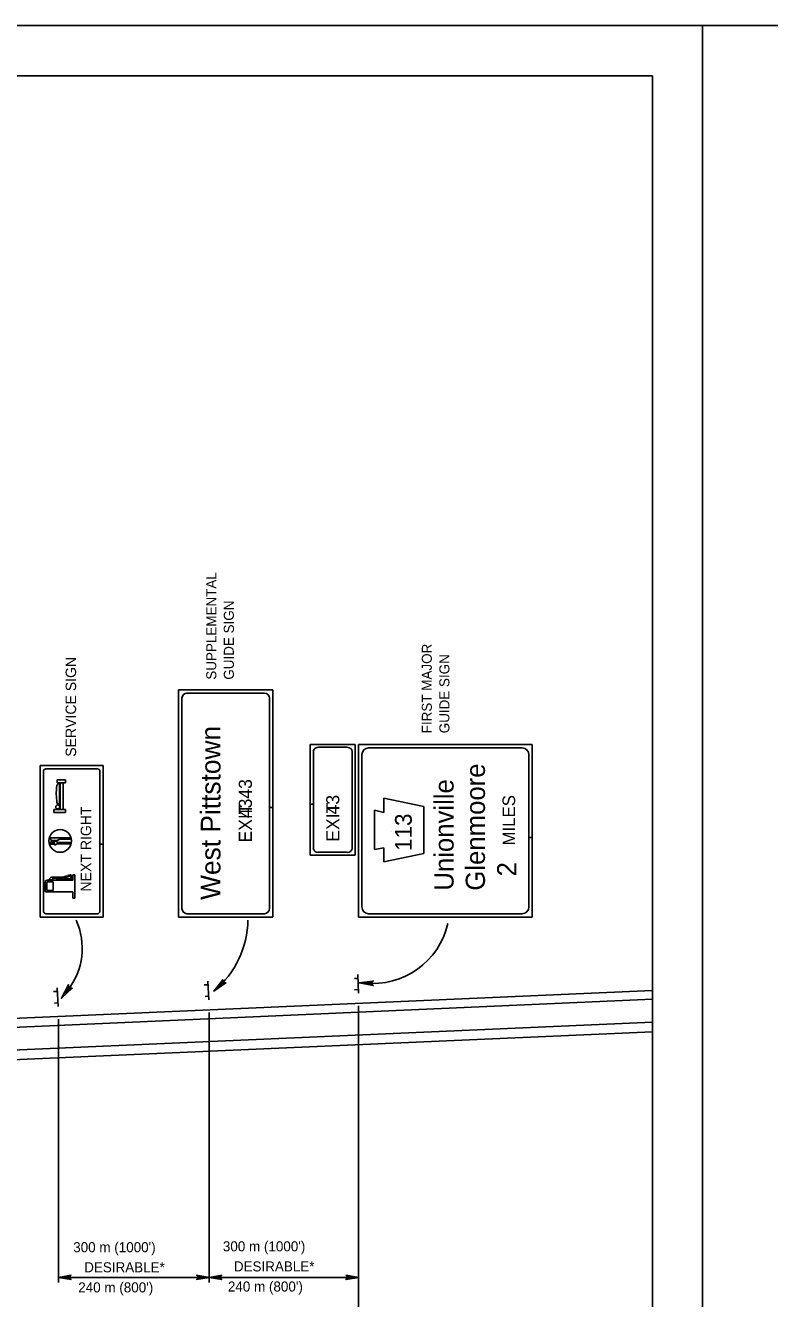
# Model space of a CAD drawing. Extents: x 640994 to 644422, y 298458 to 299646.
# Drawn here: x 642474.1 to 642696.3, y 299265.4 to 299645.6 of the extents above; entities that cross this region are included whole.
import ezdxf

# ---------------------------------------------------------------- set-up
doc = ezdxf.new("R2010")
doc.units = 0
for name, color, linetype in [('1', 7, 'Continuous'), ('2', 7, 'Continuous'), ('XCS-GRID-MIN', 7, 'Continuous')]:
    doc.layers.add(name, color=color, linetype=linetype)

msp = doc.modelspace()

# ---------------------------------------------------------------- linework, layer by layer
at = {"layer": '1'}
for p in [(641875.31, 299630.63), (642661.31, 299066.63)]:
    msp.add_line(p, (642661.31, 299630.63), dxfattribs=at)
at = {"layer": '2'}
for p, q in [((642547.94, 299447.25), (642519.81, 299447.25)), ((642519.81, 299447.25), (642519.81, 299379.38)), ((642522.31, 299446.25), (642522.31, 299446.25)), ((642522.31, 299446.25), (642545.44, 299446.25)), ((642545.44, 299446.25), (642545.44, 299446.25)), ((642547.94, 299412.11), (642547.94, 299447.25)), ((642520.81, 299381.88), (642520.81, 299444.75)), ((642546.94, 299444.75), (642546.94, 299412.11)), ((642559.06, 299413.05), (642559.06, 299430.88)), ((642559.06, 299430.88), (642572.56, 299430.88)), ((642572.56, 299430.88), (642572.56, 299397.88)), ((642625.44, 299430.88), (642573.56, 299430.88)), ((642573.56, 299430.88), (642573.56, 299379.38)), ((642625.44, 299403.13), (642625.44, 299430.88)), ((642560.06, 299428.75), (642560.06, 299413.05)), ((642570.19, 299430.13), (642561.44, 299430.13)), ((642571.69, 299399.88), (642571.69, 299428.75)), ((642574.56, 299382.38), (642574.56, 299427.88)), ((642576.56, 299429.88), (642622.44, 299429.88)), ((642624.44, 299427.88), (642624.44, 299403.13)), ((642478.44, 299379.38), (642478.44, 299424.63)), ((642478.44, 299424.63), (642497.31, 299424.63)), ((642495.56, 299423.63), (642480.19, 299423.63)), ((642497.31, 299424.63), (642497.31, 299401.1)), ((642479.44, 299422.88), (642479.44, 299381.13)), ((642483.56, 299419.5), (642483.56, 299420.38)), ((642483.56, 299420.38), (642486.06, 299420.38)), ((642483.56, 299419.5), (642486.06, 299419.5)), ((642484.44, 299411.5), (642484.44, 299419.5)), ((642485.31, 299411.5), (642485.31, 299419.5)), ((642486.06, 299419.5), (642486.06, 299420.38)), ((642496.31, 299401.1), (642496.31, 299422.88)), ((642484.19, 299413), (642484.19, 299419.25)), ((642484.44, 299415.5), (642484.44, 299415.5)), ((642546.94, 299412.11), (642547.94, 299412.11)), ((642547.94, 299412.11), (642546.94, 299412.11)), ((642546.94, 299412.11), (642546.94, 299381.88)), ((642547.94, 299379.38), (642547.94, 299412.11)), ((642559.06, 299413.05), (642560.06, 299413.05)), ((642560.06, 299413.05), (642559.06, 299413.05)), ((642559.06, 299397.88), (642559.06, 299413.05)), ((642560.06, 299413.05), (642560.06, 299399.88)), ((642565.81, 299414.38), (642565.81, 299414.38)), ((642581.06, 299410.63), (642581.06, 299414.88)), ((642581.06, 299414.88), (642593.06, 299412.38)), ((642593.06, 299412.38), (642593.06, 299405.25)), ((642615.31, 299411.75), (642615.31, 299411.75)), ((642486.06, 299411.5), (642482.56, 299411.5)), ((642482.56, 299410.63), (642482.56, 299411.5)), ((642486.06, 299410.63), (642482.56, 299410.63)), ((642486.06, 299410.63), (642486.06, 299411.5)), ((642578.31, 299405.38), (642578.31, 299411.25)), ((642578.31, 299411.25), (642581.06, 299410.63)), ((642578.31, 299399.5), (642578.31, 299405.38)), ((642583.44, 299404.88), (642583.44, 299404.88)), ((642583.44, 299404.88), (642583.44, 299404.88)), ((642583.44, 299404.88), (642583.44, 299404.88)), ((642583.44, 299404.88), (642583.44, 299404.88)), ((642593.06, 299405.5), (642593.06, 299398.38)), ((642481.44, 299401.75), (642482.56, 299402)), ((642482.81, 299401.63), (642481.44, 299401.75)), ((642482.81, 299401.5), (642481.44, 299401.63)), ((642481.44, 299401.63), (642482.81, 299401.63)), ((642481.44, 299401.38), (642482.44, 299401.5)), ((642482.94, 299401.25), (642481.44, 299401.38)), ((642481.44, 299401.13), (642482.94, 299401.25)), ((642482.81, 299401), (642481.44, 299401.13)), ((642487.31, 299403), (642481.56, 299403)), ((642481.56, 299403), (642481.56, 299402.75)), ((642483.56, 299402.25), (642481.94, 299402.25)), ((642482.44, 299401.5), (642482.81, 299401.5)), ((642487.31, 299401.63), (642483.69, 299401.63)), ((642487.31, 299401.25), (642483.69, 299401.25)), ((642487.31, 299402.63), (642484.19, 299402.63)), ((642496.31, 299401.1), (642497.31, 299401.1)), ((642497.31, 299401.1), (642496.31, 299401.1)), ((642496.31, 299381.13), (642496.31, 299401.1)), ((642497.31, 299401.1), (642497.31, 299379.38)), ((642624.44, 299403.13), (642625.44, 299403.13)), ((642625.44, 299403.13), (642624.44, 299403.13)), ((642624.44, 299403.13), (642624.44, 299382.38)), ((642625.44, 299379.38), (642625.44, 299403.13)), ((642572.56, 299397.88), (642559.06, 299397.88)), ((642561.44, 299398.75), (642570.19, 299398.75)), ((642581.06, 299400), (642578.31, 299399.5)), ((642581.06, 299395.88), (642581.06, 299400)), ((642593.06, 299398.38), (642581.06, 299395.88)), ((642479.94, 299387.25), (642479.94, 299389.88)), ((642488.19, 299390.38), (642480.31, 299390.38)), ((642482.19, 299389.88), (642480.44, 299389.88)), ((642480.44, 299387.5), (642480.44, 299389.75)), ((642480.81, 299390.38), (642481.44, 299391)), ((642481.44, 299390.5), (642481.31, 299390.38)), ((642482.19, 299390.5), (642481.44, 299390.5)), ((642481.94, 299391.25), (642485.19, 299391.25)), ((642482.19, 299391), (642485.19, 299391)), ((642482.19, 299391), (642482.19, 299390.5)), ((642482.31, 299387.5), (642482.31, 299389.63)), ((642483.31, 299390.38), (642483.31, 299390.5)), ((642483.56, 299390.75), (642486.81, 299390.75)), ((642483.56, 299390.38), (642483.56, 299390.38)), ((642483.69, 299390.5), (642487.31, 299390.5)), ((642485.81, 299391.5), (642486.56, 299391.63)), ((642485.94, 299391.13), (642486.69, 299391.38)), ((642488.19, 299390.38), (642488.19, 299392)), ((642488.81, 299392), (642488.19, 299392)), ((642488.81, 299385), (642488.81, 299392)), ((642488.19, 299386.88), (642480.31, 299386.88)), ((642482.19, 299387.25), (642480.44, 299387.25)), ((642488.19, 299385), (642488.19, 299386.88)), ((642488.81, 299385), (642488.19, 299385)), ((642497.31, 299379.38), (642478.44, 299379.38)), ((642480.19, 299380.38), (642495.56, 299380.38)), ((642519.81, 299379.38), (642547.94, 299379.38)), ((642522.31, 299380.38), (642522.31, 299380.38)), ((642545.44, 299380.38), (642522.31, 299380.38)), ((642545.44, 299380.38), (642545.44, 299380.38)), ((642573.56, 299379.38), (642625.44, 299379.38)), ((642622.44, 299380.38), (642576.56, 299380.38)), ((642573.31, 299362.25), (642573.56, 299356.63)), ((642528.56, 299359.13), (642527.44, 299359.13)), ((642528.56, 299360.25), (642528.81, 299354.63)), ((642573.44, 299361), (642572.31, 299361)), ((642170.44, 299333.13), (642661.31, 299354.84)), ((642300.56, 299341.63), (642661.31, 299357.46)), ((642483.56, 299357.13), (642482.44, 299357.13)), ((642483.56, 299358.25), (642483.81, 299352.63)), ((642528.69, 299355.75), (642527.69, 299355.63)), ((642573.56, 299357.75), (642572.31, 299357.63)), ((642483.81, 299353.75), (642482.69, 299353.63)), ((642528.94, 299352.38), (642528.94, 299352.38)), ((642528.94, 299350.88), (642528.94, 299270.25)), ((642573.56, 299354.38), (642573.56, 299354.38)), ((642573.56, 299352.88), (642573.56, 299234.75)), ((642171.94, 299326.5), (642661.31, 299347.96)), ((642483.94, 299348.88), (642483.94, 299270.25)), ((642297.31, 299329.13), (642661.31, 299345.09)), ((642528.94, 299271.75), (642483.94, 299271.75)), ((642573.56, 299271.75), (642528.94, 299271.75))]:
    msp.add_line(p, q, dxfattribs=at)
for points in [[(642487.78, 299358.09), (642487.52, 299358.19), (642484.82, 299355.14), (642487.78, 299358.09), (642488.03, 299358.11), (642484.82, 299355.14), (642487.1, 299358.52), (642486.95, 299358.76), (642484.82, 299355.14), (642486.92, 299359.13), (642486.95, 299358.76)], [(642533.69, 299359.7), (642533.31, 299359.8), (642530.36, 299357.21), (642533.69, 299359.7), (642533.94, 299359.72), (642530.36, 299357.21), (642533.03, 299360.16), (642533.01, 299360.4), (642530.36, 299357.21), (642533, 299360.65), (642533.01, 299360.4)], [(642577.56, 299359.25), (642577.56, 299359.5), (642573.69, 299359.75), (642577.56, 299359.25), (642577.94, 299358.88), (642573.69, 299359.75), (642577.56, 299359.88), (642577.69, 299360.25), (642573.69, 299359.75), (642577.94, 299360.25), (642577.69, 299360.25)], [(642487.44, 299271.25), (642487.31, 299271.5), (642483.94, 299271.75), (642487.44, 299271.25), (642487.69, 299271.13), (642483.94, 299271.75), (642487.31, 299271.88), (642487.44, 299272.13), (642483.94, 299271.75), (642487.69, 299272.38), (642487.44, 299272.13)], [(642525.44, 299272.25), (642525.56, 299272), (642528.94, 299271.75), (642525.44, 299272.25), (642525.19, 299272.38), (642528.94, 299271.75), (642525.56, 299271.63), (642525.44, 299271.38), (642528.94, 299271.75), (642525.19, 299271.13), (642525.44, 299271.38)], [(642532.44, 299271.25), (642532.31, 299271.5), (642528.94, 299271.75), (642532.44, 299271.25), (642532.69, 299271.13), (642528.94, 299271.75), (642532.31, 299271.88), (642532.44, 299272.13), (642528.94, 299271.75), (642532.69, 299272.38), (642532.44, 299272.13)], [(642570.06, 299272.25), (642570.19, 299272), (642573.56, 299271.75), (642570.06, 299272.25), (642569.81, 299272.38), (642573.56, 299271.75), (642570.19, 299271.63), (642570.06, 299271.38), (642573.56, 299271.75), (642569.81, 299271.13), (642570.06, 299271.38)]]:
    msp.add_lwpolyline(points, dxfattribs=at)
for centre, radius in [((642483.71, 299412.25), 0.598), ((642484.44, 299402.1), 3.38)]:
    msp.add_circle(centre, radius, dxfattribs=at)
for centre, radius, start, end in [((642522.31, 299444.75), 1.5, 90, 180), ((642545.44, 299444.75), 1.5, 0, 90), ((642576.56, 299427.88), 2, 90, 180), ((642622.44, 299427.88), 2, 0, 90), ((642480.19, 299422.88), 0.75, 90, 180), ((642495.56, 299422.88), 0.75, 0, 90), ((642484.19, 299418.52), 0.74, 84.1655, 172.9293), ((642498.81, 299416.24), 15.54, 171.2295, 181.1783), ((642502.02, 299416.2), 18.75, 180.8408, 188.1781), ((642484.26, 299413.87), 0.868, 202.8419, 269.9082), ((642481.93, 299402.7), 0.422, 180, 270), ((642482.81, 299401.21), 0.83, 44.7019, 103.537), ((642482.86, 299401.64), 0.724, 261.5401, 313.94), ((642483.74, 299400.8), 0.494, 95.8318, 139.6318), ((642483.69, 299402.09), 0.42, 224.9301, 269.654), ((642483.42, 299402.96), 0.696, 281.1263, 314.137), ((642484.17, 299402.21), 0.369, 83.1408, 137.1102), ((642487.26, 299402.79), 0.218, 261.5053, 98.4947), ((642487.26, 299401.48), 0.195, 258.6255, 101.3745), ((642480.33, 299389.94), 0.405, 97.9024, 178.9277), ((642480.6, 299389.69), 0.228, 107.0861, 183.3769), ((642482.02, 299390.47), 0.826, 95.5404, 137.2088), ((642482.09, 299389.59), 0.327, 355.7148, 73.5391), ((642483.61, 299390.52), 0.265, 89.4256, 167.8581), ((642483.71, 299390.43), 0.0642, 79.1965, 181.8396), ((642484.89, 299393.75), 2.48, 276.6108, 292.2765), ((642484.89, 299393.75), 2.79, 276.6108, 292.2765), ((642487.53, 299389.71), 2.24, 92.3973, 115.3499), ((642487.31, 299390.24), 1.32, 82.2446, 117.6633), ((642486.88, 299392.05), 1.27, 271.1053, 299.4807), ((642487.29, 299391.29), 0.794, 269.2148, 356.6422), ((642487.38, 299391.25), 0.7, 359.2139, 85.3444), ((642487.39, 299391.24), 0.318, 289.9687, 73.0966), ((642480.27, 299387.19), 0.346, 171.6254, 276.5874), ((642480.58, 299387.49), 0.207, 168.286, 258.2569), ((642482.15, 299387.55), 0.262, 276.241, 356.6554), ((642522.31, 299381.88), 1.5, 180, 270), ((642545.44, 299381.88), 1.5, 270, 0), ((642576.56, 299382.38), 2, 180, 270), ((642622.44, 299382.38), 2, 270, 0), ((642480.19, 299381.13), 0.75, 180, 270), ((642470.61, 299370.01), 20.4, 321.9627, 24.5125), ((642495.56, 299381.13), 0.75, 270, 0), ((642512.26, 299378.97), 28.27, 310.2091, 358.9986), ((642577.85, 299382.49), 22.95, 263.5843, 347.307)]:
    msp.add_arc(centre, radius, start, end, dxfattribs=at)
for centre, major_axis, start_param, end_param in [((642561.45, 299428.77), (-1.41, 0), 4.712389, 6.283185), ((642570.24, 299428.77), (-1.41, 0), 3.141593, 4.712389), ((642561.45, 299399.96), (1.41, 0), 3.141593, 4.712389), ((642570.24, 299399.96), (1.41, 0), 4.712389, 6.283185)]:
    msp.add_ellipse(centre, major_axis=major_axis, ratio=0.910229, start_param=start_param, end_param=end_param, dxfattribs=at)
at = {"layer": 'XCS-GRID-MIN'}
for points in [[(641835.31, 299645.63), (642676.31, 299645.63), (642676.31, 299051.63), (641835.31, 299051.63)], [(642676.31, 299645.63), (643517.31, 299645.63), (643517.31, 299051.63), (642676.31, 299051.63)]]:
    msp.add_lwpolyline(points, close=True, dxfattribs=at)

# ---------------------------------------------------------------- texts
at = {"layer": '2'}
for s, height, p in [('SUPPLEMENTAL', 3, (642531.06, 299450.25)), ('GUIDE SIGN', 3, (642536.31, 299450.25)), ('FIRST MAJOR', 3, (642595.44, 299434.25)), ('GUIDE SIGN', 3, (642600.69, 299434.25)), ('SERVICE SIGN', 3.1342, (642489.19, 299427.25)), ('West Pittstown', 5.8747, (642532.31, 299384.5)), ('Glenmoore', 5.743, (642611.31, 299387.25)), ('EXIT 43', 3.918, (642541.69, 299401.63)), ('Unionville', 5.743, (642601.94, 299387.25)), ('     43', 3.918, (642567.81, 299402.75)), ('MILES', 3.75, (642620.31, 299400.75)), ('NEXT RIGHT', 3.134, (642493.69, 299387)), ('     43', 3.918, (642541.69, 299401.63)), ('EXIT   ', 3.918, (642567.81, 299401.88)), ('113', 5, (642589.44, 299399.13)), ('  2 ', 5.743, (642620.69, 299387.25))]:
    msp.add_text(s, height=height, rotation=90, dxfattribs=at).set_placement(p)
for s, p in [("300 m (1000')", (642488.33, 299279.28)), ("300 m (1000')", (642533.03, 299279.54)), (' DESIRABLE*', (642490.49, 299273.28)), (' DESIRABLE*', (642535.19, 299273.54)), ("240 m (800')", (642489.83, 299267.28)), ("240 m (800')", (642534.53, 299267.54))]:
    msp.add_text(s, height=3, dxfattribs=at).set_placement(p)

doc.saveas('drawing.dxf')
